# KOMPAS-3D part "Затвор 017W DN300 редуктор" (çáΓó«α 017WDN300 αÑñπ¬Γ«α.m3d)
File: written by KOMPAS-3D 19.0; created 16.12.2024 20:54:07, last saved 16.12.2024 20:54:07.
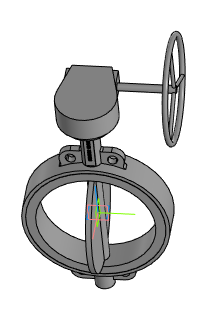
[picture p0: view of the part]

Document properties: Автор: Евгений; Полное имя файла: ..\Затвор 017WDN300 редуктор.a3d

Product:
- Part/product: Затвор 017W DN300 редуктор
    Масса: 51.8255

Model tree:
1. Операция без истории:1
